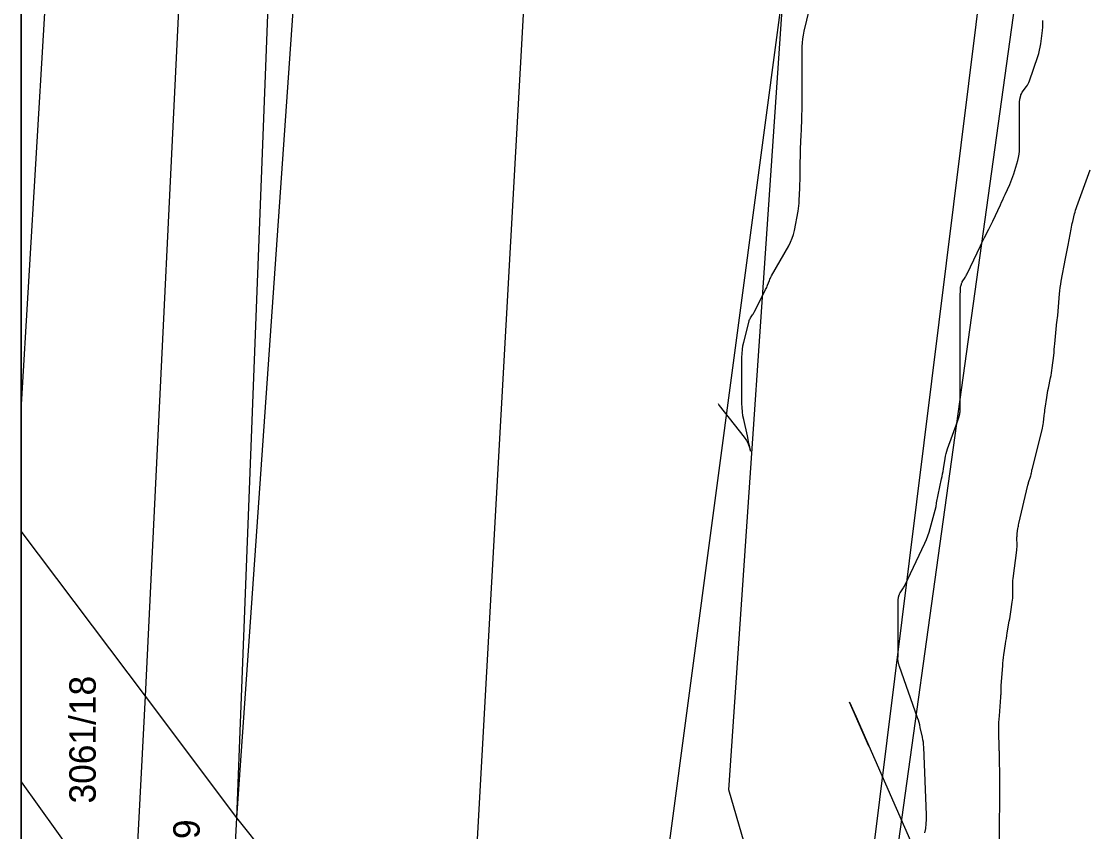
# Model space of a CAD drawing. Extents: x -534410 to -534262, y -1190162 to -1189584.
# Drawn here: x -534410.13 to -534375.9, y -1189946.36 to -1189920.28 of the extents above; entities that cross this region are included whole.
import ezdxf

# ---------------------------------------------------------------- set-up
doc = ezdxf.new("R2010")
doc.units = 0
for name, color, linetype in [('30', 7, 'Continuous'), ('31', 7, 'Continuous'), ('_rámeček', 7, 'Continuous'), ('_rámeček_mřížka', 7, 'Continuous'), ('Hranice parcel', 7, 'Continuous'), ('Parcelní čísla', 7, 'Continuous')]:
    doc.layers.add(name, color=color, linetype=linetype)

msp = doc.modelspace()

# ---------------------------------------------------------------- linework, layer by layer
at = {"layer": '30'}
for points in [[(-534381.07, -1189946.397), (-534381.043, -1189946.252), (-534381.026, -1189946.106), (-534381.017, -1189945.96), (-534381.018, -1189945.813), (-534381.106, -1189943.637), (-534381.111, -1189943.556), (-534381.119, -1189943.476), (-534381.132, -1189943.397), (-534381.147, -1189943.318), (-534381.217, -1189943.002), (-534381.235, -1189942.924), (-534381.256, -1189942.846), (-534381.279, -1189942.769), (-534381.305, -1189942.692), (-534381.886, -1189941.039), (-534381.893, -1189941.02), (-534381.899, -1189941.001), (-534381.904, -1189940.981), (-534381.909, -1189940.962), (-534381.928, -1189940.884), (-534381.932, -1189940.864), (-534381.935, -1189940.844), (-534381.937, -1189940.824), (-534381.937, -1189940.804), (-534381.933, -1189940.703), (-534381.932, -1189940.68), (-534381.932, -1189940.656), (-534381.932, -1189940.633), (-534381.931, -1189940.609), (-534381.931, -1189939.08), (-534381.931, -1189939.056), (-534381.931, -1189939.033), (-534381.931, -1189939.009), (-534381.93, -1189938.986), (-534381.927, -1189938.881), (-534381.925, -1189938.863), (-534381.923, -1189938.845), (-534381.92, -1189938.827), (-534381.915, -1189938.809), (-534381.895, -1189938.738), (-534381.889, -1189938.721), (-534381.883, -1189938.704), (-534381.874, -1189938.687), (-534381.865, -1189938.672), (-534381.779, -1189938.543), (-534381.761, -1189938.516), (-534381.745, -1189938.488), (-534381.73, -1189938.46), (-534381.716, -1189938.432), (-534381.068, -1189937.07), (-534381.017, -1189936.956), (-534380.972, -1189936.841), (-534380.932, -1189936.723), (-534380.898, -1189936.603), (-534380.713, -1189935.899), (-534380.711, -1189935.889), (-534380.709, -1189935.879), (-534380.707, -1189935.87), (-534380.706, -1189935.86), (-534380.701, -1189935.82), (-534380.7, -1189935.81), (-534380.698, -1189935.8), (-534380.696, -1189935.79), (-534380.694, -1189935.78), (-534380.533, -1189935.007), (-534380.516, -1189934.925), (-534380.501, -1189934.844), (-534380.487, -1189934.763), (-534380.474, -1189934.681), (-534380.423, -1189934.354), (-534380.408, -1189934.273), (-534380.389, -1189934.192), (-534380.367, -1189934.113), (-534380.34, -1189934.035), (-534380.017, -1189933.156), (-534380.006, -1189933.126), (-534379.996, -1189933.095), (-534379.988, -1189933.064), (-534379.98, -1189933.033), (-534379.952, -1189932.907), (-534379.946, -1189932.876), (-534379.941, -1189932.844), (-534379.939, -1189932.812), (-534379.938, -1189932.78), (-534379.938, -1189930.892), (-534379.938, -1189930.868), (-534379.937, -1189930.845), (-534379.937, -1189930.821), (-534379.936, -1189930.797), (-534379.933, -1189930.703), (-534379.932, -1189930.68), (-534379.932, -1189930.656), (-534379.931, -1189930.633), (-534379.931, -1189930.609), (-534379.931, -1189929.08), (-534379.931, -1189929.056), (-534379.931, -1189929.033), (-534379.93, -1189929.009), (-534379.93, -1189928.986), (-534379.926, -1189928.882), (-534379.925, -1189928.863), (-534379.923, -1189928.845), (-534379.92, -1189928.826), (-534379.916, -1189928.808), (-534379.897, -1189928.736), (-534379.892, -1189928.718), (-534379.885, -1189928.701), (-534379.877, -1189928.684), (-534379.868, -1189928.668), (-534379.779, -1189928.527), (-534379.762, -1189928.498), (-534379.745, -1189928.469), (-534379.729, -1189928.439), (-534379.714, -1189928.408), (-534379.283, -1189927.502), (-534379.251, -1189927.435), (-534379.218, -1189927.369), (-534379.185, -1189927.303), (-534379.151, -1189927.237), (-534379.014, -1189926.975), (-534378.98, -1189926.91), (-534378.947, -1189926.844), (-534378.914, -1189926.777), (-534378.883, -1189926.71), (-534378.64, -1189926.188), (-534378.602, -1189926.106), (-534378.564, -1189926.023), (-534378.527, -1189925.941), (-534378.489, -1189925.859), (-534378.339, -1189925.53), (-534378.303, -1189925.447), (-534378.27, -1189925.363), (-534378.24, -1189925.278), (-534378.213, -1189925.192), (-534378.086, -1189924.762), (-534378.06, -1189924.661), (-534378.042, -1189924.559), (-534378.03, -1189924.455), (-534378.027, -1189924.351), (-534378.027, -1189923.199), (-534378.027, -1189923.164), (-534378.027, -1189923.128), (-534378.027, -1189923.093), (-534378.027, -1189923.057), (-534378.028, -1189922.904), (-534378.027, -1189922.874), (-534378.025, -1189922.845), (-534378.021, -1189922.816), (-534378.015, -1189922.787), (-534377.988, -1189922.671), (-534377.98, -1189922.643), (-534377.969, -1189922.615), (-534377.956, -1189922.59), (-534377.94, -1189922.565), (-534377.801, -1189922.374), (-534377.774, -1189922.333), (-534377.75, -1189922.291), (-534377.729, -1189922.247), (-534377.711, -1189922.201), (-534377.442, -1189921.418), (-534377.409, -1189921.316), (-534377.383, -1189921.213), (-534377.361, -1189921.109), (-534377.345, -1189921.003), (-534377.291, -1189920.578), (-534377.28, -1189920.472), (-534377.274, -1189920.365), (-534377.273, -1189920.259)], [(-534382.868, -1189943.609), (-534383.492, -1189942.189), (-534383.296, -1189942.636), (-534381.381, -1189946.992)]]:
    msp.add_lwpolyline(points, dxfattribs=at)
at = {"layer": '31'}
for points in [[(-534387.715, -1189932.58), (-534387.697, -1189932.621), (-534387.694, -1189932.628), (-534387.691, -1189932.634), (-534387.687, -1189932.64), (-534387.682, -1189932.646), (-534386.878, -1189933.668), (-534386.808, -1189933.769), (-534386.752, -1189933.876), (-534386.71, -1189933.99), (-534386.682, -1189934.109), (-534386.704, -1189933.987), (-534386.727, -1189933.865), (-534386.752, -1189933.743), (-534386.778, -1189933.621), (-534386.896, -1189933.099), (-534386.922, -1189932.972), (-534386.94, -1189932.843), (-534386.95, -1189932.713), (-534386.954, -1189932.583), (-534386.954, -1189931.094), (-534386.95, -1189930.97), (-534386.939, -1189930.846), (-534386.92, -1189930.724), (-534386.893, -1189930.603), (-534386.725, -1189929.934), (-534386.717, -1189929.906), (-534386.706, -1189929.879), (-534386.693, -1189929.853), (-534386.678, -1189929.828), (-534386.612, -1189929.729), (-534386.596, -1189929.704), (-534386.58, -1189929.679), (-534386.566, -1189929.653), (-534386.552, -1189929.627), (-534386.193, -1189928.916), (-534386.175, -1189928.88), (-534386.158, -1189928.844), (-534386.143, -1189928.807), (-534386.128, -1189928.769), (-534386.072, -1189928.619), (-534386.057, -1189928.582), (-534386.04, -1189928.546), (-534386.023, -1189928.51), (-534386.004, -1189928.475), (-534385.449, -1189927.504), (-534385.388, -1189927.386), (-534385.337, -1189927.264), (-534385.296, -1189927.138), (-534385.266, -1189927.008), (-534385.15, -1189926.395), (-534385.135, -1189926.306), (-534385.123, -1189926.218), (-534385.115, -1189926.129), (-534385.109, -1189926.039), (-534385.093, -1189925.666), (-534385.09, -1189925.584), (-534385.087, -1189925.502), (-534385.085, -1189925.42), (-534385.084, -1189925.337), (-534385.081, -1189925.009), (-534385.08, -1189924.927), (-534385.079, -1189924.845), (-534385.077, -1189924.762), (-534385.075, -1189924.68), (-534385.065, -1189924.314), (-534385.063, -1189924.238), (-534385.06, -1189924.163), (-534385.057, -1189924.087), (-534385.053, -1189924.011), (-534385.038, -1189923.709), (-534385.034, -1189923.633), (-534385.031, -1189923.558), (-534385.028, -1189923.482), (-534385.026, -1189923.406), (-534385.016, -1189923.023), (-534385.014, -1189922.934), (-534385.013, -1189922.844), (-534385.012, -1189922.755), (-534385.012, -1189922.666), (-534385.012, -1189921.093), (-534385.008, -1189920.969), (-534384.997, -1189920.846), (-534384.979, -1189920.724), (-534384.953, -1189920.603), (-534384.78, -1189919.894)], [(-534378.672, -1189946.614), (-534378.666, -1189945.96), (-534378.666, -1189945.922), (-534378.666, -1189945.883), (-534378.666, -1189945.806), (-534378.666, -1189945.767), (-534378.665, -1189945.729), (-534378.66, -1189945.075), (-534378.659, -1189944.96), (-534378.659, -1189944.845), (-534378.66, -1189944.729), (-534378.662, -1189944.614), (-534378.674, -1189943.947), (-534378.675, -1189943.913), (-534378.675, -1189943.879), (-534378.676, -1189943.811), (-534378.676, -1189943.777), (-534378.677, -1189943.743), (-534378.689, -1189943.065), (-534378.69, -1189942.955), (-534378.688, -1189942.845), (-534378.683, -1189942.735), (-534378.676, -1189942.625), (-534378.627, -1189942.027), (-534378.624, -1189941.997), (-534378.623, -1189941.966), (-534378.622, -1189941.935), (-534378.621, -1189941.904), (-534378.619, -1189941.781), (-534378.618, -1189941.75), (-534378.617, -1189941.72), (-534378.616, -1189941.689), (-534378.614, -1189941.658), (-534378.568, -1189941.023), (-534378.561, -1189940.934), (-534378.552, -1189940.845), (-534378.541, -1189940.756), (-534378.529, -1189940.667), (-534378.477, -1189940.313), (-534378.464, -1189940.225), (-534378.45, -1189940.137), (-534378.436, -1189940.048), (-534378.421, -1189939.96), (-534378.355, -1189939.578), (-534378.343, -1189939.505), (-534378.331, -1189939.431), (-534378.319, -1189939.358), (-534378.308, -1189939.285), (-534378.259, -1189938.969), (-534378.251, -1189938.907), (-534378.245, -1189938.844), (-534378.242, -1189938.781), (-534378.242, -1189938.718), (-534378.246, -1189938.466), (-534378.245, -1189938.403), (-534378.243, -1189938.34), (-534378.238, -1189938.278), (-534378.232, -1189938.215), (-534378.116, -1189937.295), (-534378.111, -1189937.25), (-534378.107, -1189937.205), (-534378.106, -1189937.16), (-534378.106, -1189937.115), (-534378.11, -1189936.926), (-534378.11, -1189936.885), (-534378.108, -1189936.845), (-534378.105, -1189936.804), (-534378.1, -1189936.764), (-534378.078, -1189936.602), (-534378.071, -1189936.562), (-534378.064, -1189936.522), (-534378.056, -1189936.482), (-534378.048, -1189936.442), (-534377.757, -1189935.206), (-534377.75, -1189935.177), (-534377.742, -1189935.147), (-534377.734, -1189935.118), (-534377.725, -1189935.09), (-534377.676, -1189934.935), (-534377.668, -1189934.908), (-534377.654, -1189934.863), (-534377.652, -1189934.854), (-534377.65, -1189934.844), (-534377.648, -1189934.835), (-534377.646, -1189934.826), (-534377.636, -1189934.761), (-534377.633, -1189934.747), (-534377.631, -1189934.733), (-534377.628, -1189934.719), (-534377.624, -1189934.705), (-534377.304, -1189933.427), (-534377.291, -1189933.369), (-534377.279, -1189933.312), (-534377.269, -1189933.254), (-534377.261, -1189933.195), (-534377.231, -1189932.961), (-534377.224, -1189932.903), (-534377.216, -1189932.845), (-534377.209, -1189932.786), (-534377.201, -1189932.728), (-534377.154, -1189932.387), (-534377.143, -1189932.311), (-534377.13, -1189932.235), (-534377.116, -1189932.159), (-534377.1, -1189932.084), (-534377.027, -1189931.755), (-534377.011, -1189931.675), (-534376.996, -1189931.595), (-534376.984, -1189931.514), (-534376.974, -1189931.433), (-534376.929, -1189931.032), (-534376.918, -1189930.938), (-534376.908, -1189930.844), (-534376.899, -1189930.75), (-534376.89, -1189930.656), (-534376.825, -1189929.957), (-534376.823, -1189929.94), (-534376.821, -1189929.923), (-534376.819, -1189929.906), (-534376.816, -1189929.889), (-534376.806, -1189929.821), (-534376.803, -1189929.804), (-534376.801, -1189929.787), (-534376.799, -1189929.77), (-534376.798, -1189929.753), (-534376.741, -1189929.054), (-534376.731, -1189928.949), (-534376.718, -1189928.845), (-534376.703, -1189928.742), (-534376.685, -1189928.638), (-534376.548, -1189927.912), (-534376.467, -1189927.481), (-534376.37, -1189926.967), (-534376.358, -1189926.906), (-534376.346, -1189926.845), (-534376.332, -1189926.784), (-534376.318, -1189926.723), (-534376.259, -1189926.48), (-534376.243, -1189926.419), (-534376.226, -1189926.359), (-534376.207, -1189926.3), (-534376.187, -1189926.241), (-534375.76, -1189925.061)]]:
    msp.add_lwpolyline(points, dxfattribs=at)
at = {"layer": '_rámeček'}
msp.add_line((-534410.126, -1189584.47), (-534410.126, -1190161.97), dxfattribs=at)
msp.add_lwpolyline([(-534410.126, -1189899.47), (-534261.626, -1189899.47), (-534261.626, -1190004.47), (-534410.126, -1190004.47)], close=True, dxfattribs=at)
at = {"layer": '_rámeček_mřížka'}
msp.add_line((-534410.126, -1189584.47), (-534410.126, -1190161.97), dxfattribs=at)
at = {"layer": 'Hranice parcel'}
for p, q in [((-534403.19, -1189945.91), (-534398.3, -1189817.87)), ((-534391.18, -1189961.04), (-534385.61, -1189919.11)), ((-534406.13, -1189942), (-534410.126, -1189936.685)), ((-534406.54, -1189949.77), (-534406.13, -1189942)), ((-534403.19, -1189945.91), (-534406.13, -1189942)), ((-534410.126, -1189944.756), (-534406.54, -1189949.77)), ((-534403.61, -1189953.7), (-534403.19, -1189945.91)), ((-534395.93, -1189955.06), (-534403.19, -1189945.91))]:
    msp.add_line(p, q, dxfattribs=at)
for points in [[(-534395.93, -1189955.06), (-534393.76, -1189916.2), (-534389.49, -1189774.63), (-534390.92, -1189749.37)], [(-534383.94, -1189956.8), (-534379.19, -1189918.48), (-534376.74, -1189853.94), (-534375.92, -1189797.44), (-534376.41, -1189774.02), (-534378.12, -1189750.26)], [(-534406.13, -1189942), (-534403.45, -1189886.77), (-534402.68, -1189837.82), (-534401.95, -1189776.76), (-534406.3, -1189754), (-534406.48, -1189752.31)], [(-534373.61, -1189764.09), (-534375.04, -1189897.07), (-534384.28, -1189963.65)], [(-534410.126, -1189932.794), (-534408.16, -1189899.66), (-534406.57, -1189847.9), (-534405.68, -1189781.38), (-534406.95, -1189766.9)], [(-534403.19, -1189945.91), (-534400.52, -1189907.49), (-534398.39, -1189858.23), (-534398.3, -1189817.87)], [(-534383.94, -1189956.8), (-534387.37, -1189945.01), (-534385.61, -1189919.11)]]:
    msp.add_lwpolyline(points, dxfattribs=at)

# ---------------------------------------------------------------- texts
at = {"layer": 'Parcelní čísla'}
for s, p in [('3061/18', (-534407.732, -1189945.451)), ('3061/19', (-534404.39, -1189950.071))]:
    msp.add_text(s, height=0.85, rotation=90, dxfattribs=at).set_placement(p)

doc.saveas('drawing.dxf')
